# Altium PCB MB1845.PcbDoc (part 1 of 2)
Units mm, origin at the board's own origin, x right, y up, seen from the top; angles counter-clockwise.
Board outline 43.1 x 47.12 mm, 4 copper layers (Top Layer, Internal 1, Internal 2, Bottom Layer), stack 1.565 mm thick; 96 components, 86 nets, 349 pads, 596 vias.
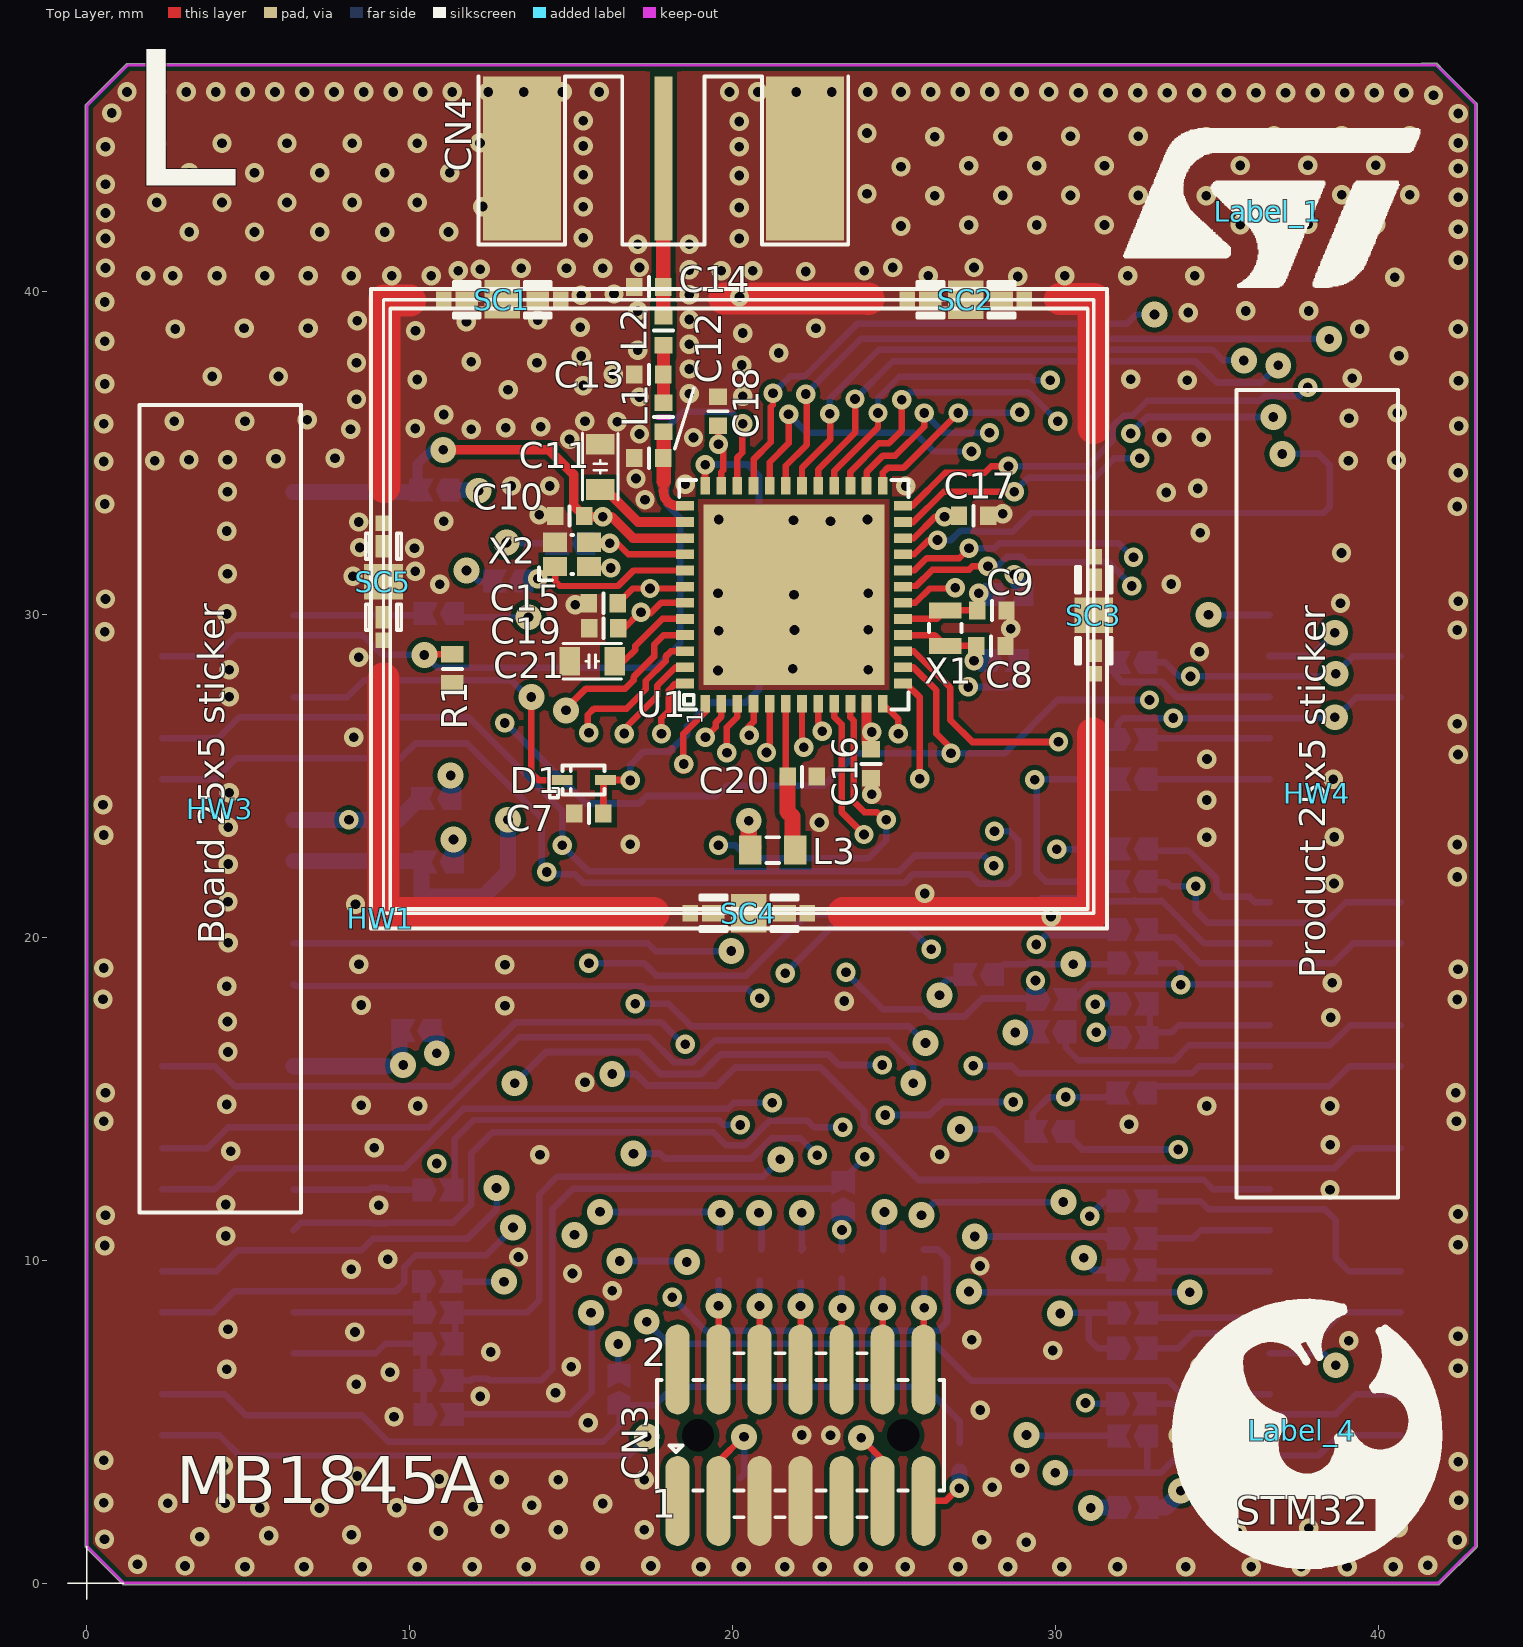
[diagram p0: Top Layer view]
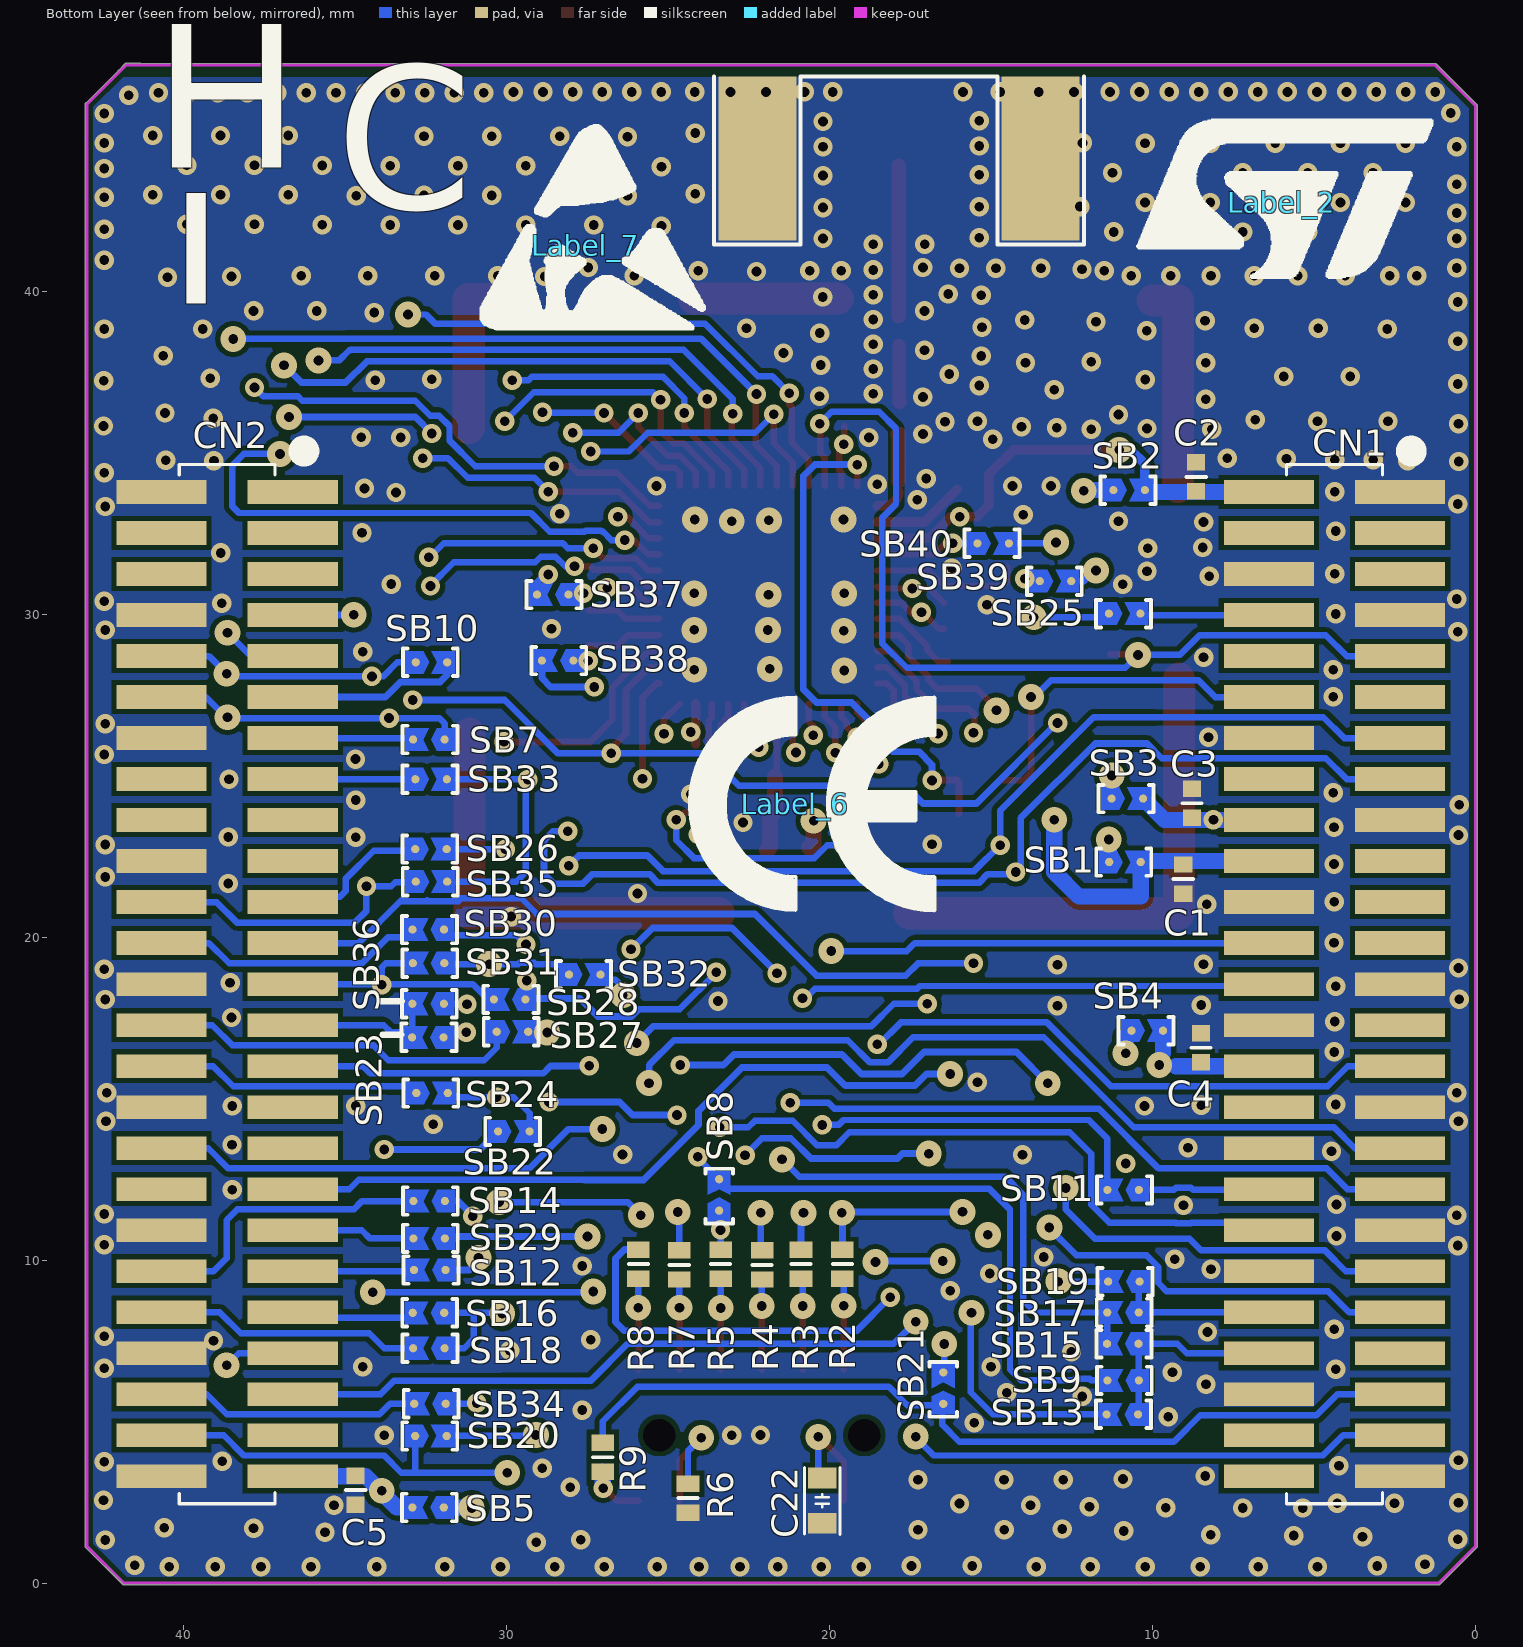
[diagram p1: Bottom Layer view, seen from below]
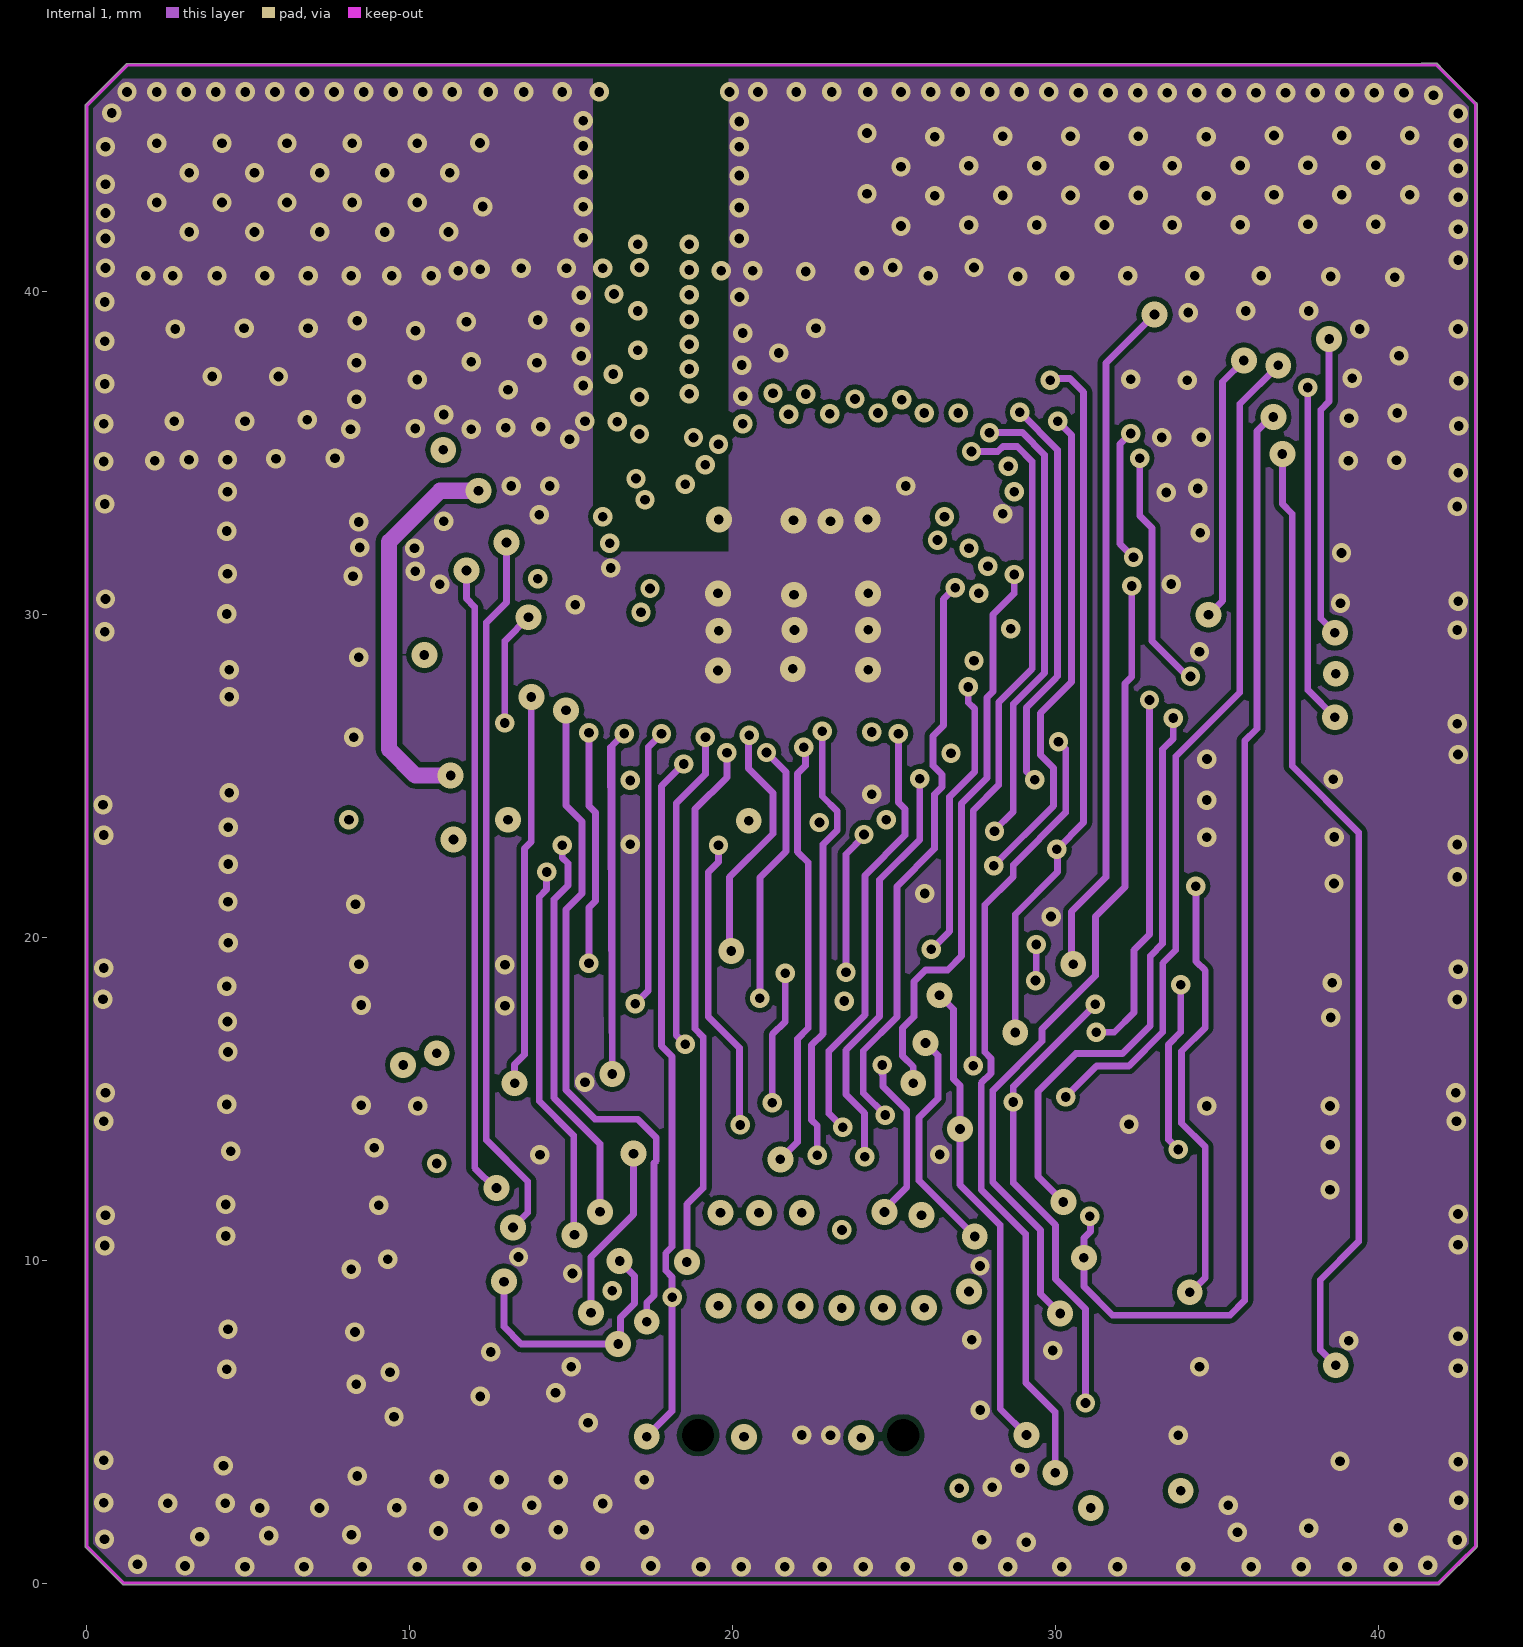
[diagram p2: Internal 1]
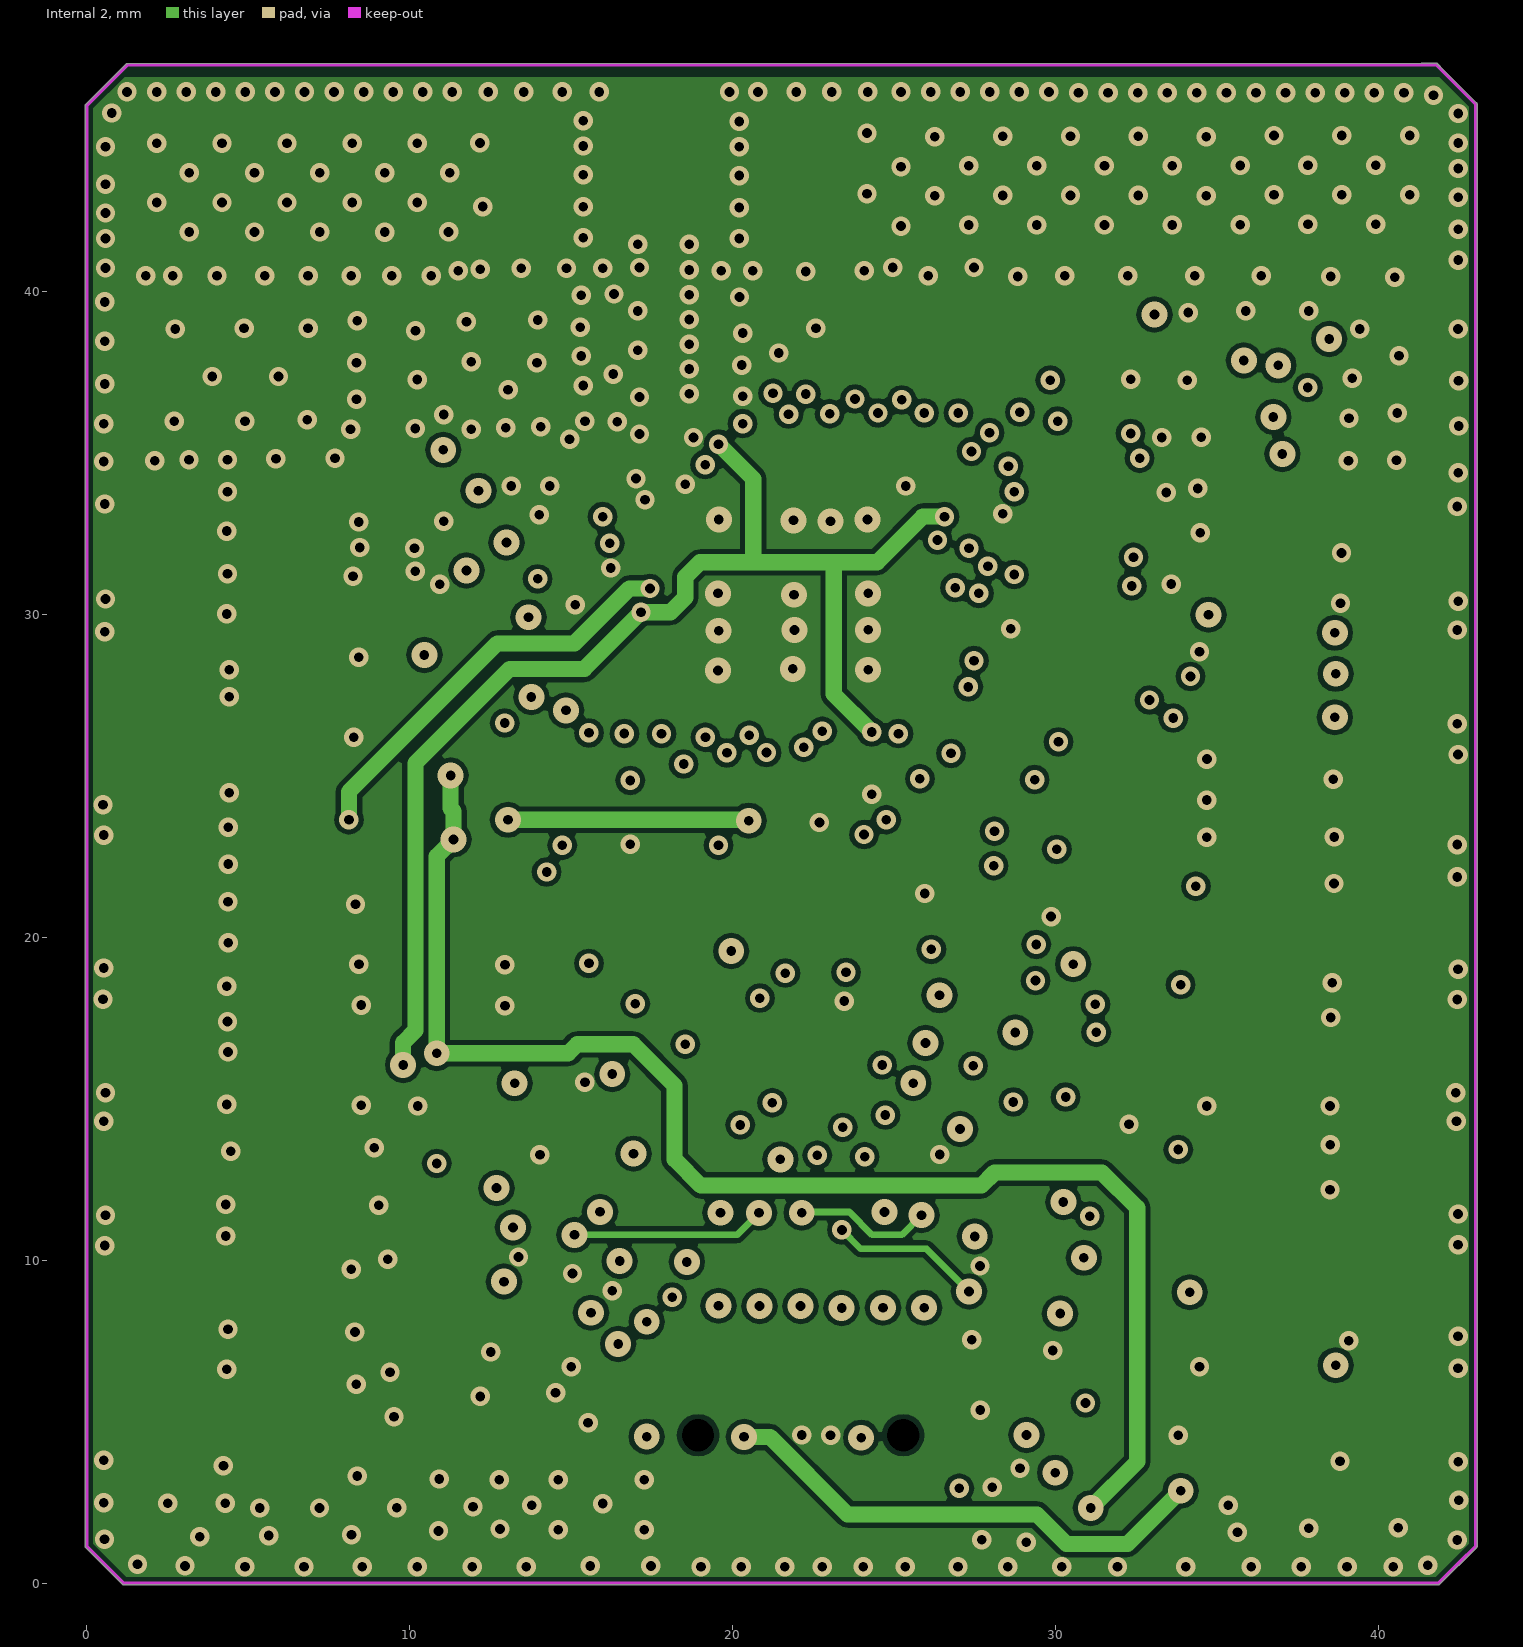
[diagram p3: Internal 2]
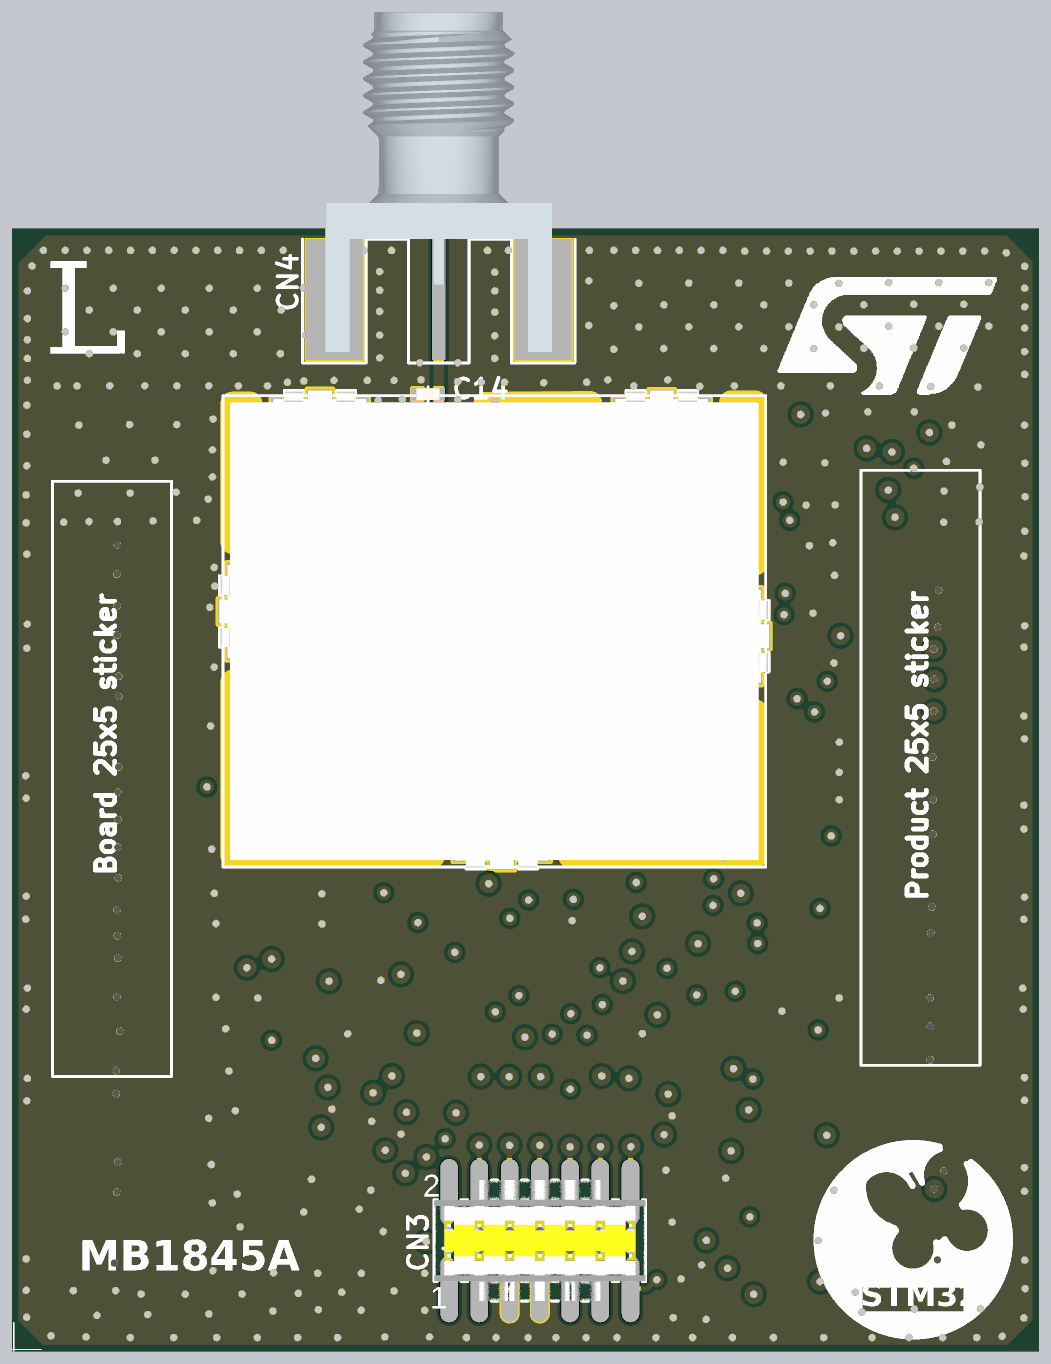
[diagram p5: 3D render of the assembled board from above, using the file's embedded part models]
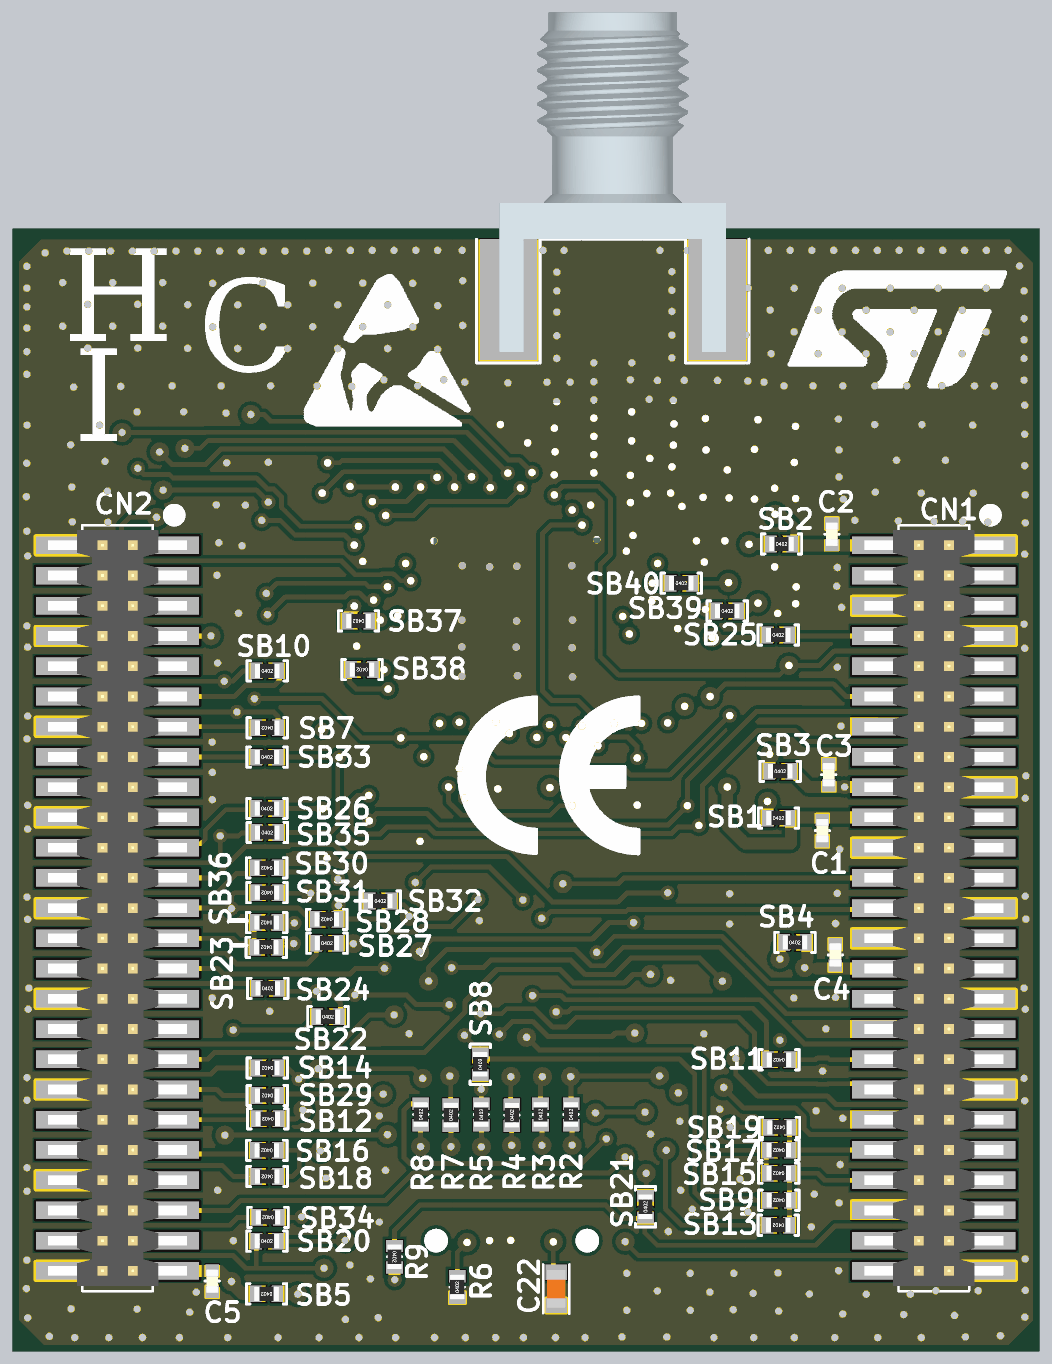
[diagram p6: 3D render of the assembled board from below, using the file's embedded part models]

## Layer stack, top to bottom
Top Solder: solder mask 0.0178, Solder Resist, Dk 4.2
Top Layer: signal copper 0.0406
Dielectric 1: core 0.0762, FR-4, Dk 3.7
Internal 1: signal copper 0.0305
Dielectric 3: prepreg 1.27, Dk 4.5
Internal 2: signal copper 0.0305
Dielectric 2: core 0.0762, Dk 3.7
Bottom Layer: signal copper 0.0406
Bottom Solder: solder mask 0.0178, Solder Resist, Dk 4.2

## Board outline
-0.036,1.103 cw(c0,1.139) -0.05,1.139 -0.05,45.75 -0.05,45.755 cw(c0,45.755) -0.035,45.791 -0.036,45.791 1.209,47.036 1.209,47.035 cw(c1.245,47) 1.245,47.05 41.326,47.066 cw(c41.326,47.015) 41.326,47.066 41.78,47.066 cw(c41.78,47.015) 41.816,47.051 42.023,46.844 43.03,45.837 cw(c43.001,45.795) 43.051,45.795 cw(c43.001,45.795) 43.05,45.785 43.05,1.151 cw(c43.001,1.141) 43.051,1.141 cw(c43.001,1.141) 43.037,1.105 41.888,-0.036 cw(c41.852,0) 41.852,-0.05 1.139,-0.05 cw(c1.139,0) 1.103,-0.036

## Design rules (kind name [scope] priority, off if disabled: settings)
Clearance "RF Path 3" [InNet('NetC12_2')] p1: gap=0.13 ignorepadtopadclearanceinfootprint=FALSE
Clearance "RF Path 2" [InNet('NetC13_2')] p2: gap=0.13 ignorepadtopadclearanceinfootprint=FALSE
Clearance "RF Path 1" [InNet('ANT')] p3: gap=0.13 ignorepadtopadclearanceinfootprint=FALSE
Clearance [All] p4: gap=0.15 ignorepadtopadclearanceinfootprint=FALSE
ComponentClearance [All] p1: gap=0.2 collisioncheckmode=3 verticalgap=0.2 showdistances=FALSE
HoleSize [All] p1: absolutevalues=TRUE maxlimit=10 minlimit=0.025 maxpercent=80.000 minpercent=20.000
MinimumSolderMaskSliver [All] p1 off: minsoldermaskwidth=0.1
PasteMaskExpansion [All] p1 off: expansion=0
PlaneConnect [All] p1: planeconnectstyle=Relief reliefexpansion=0.508 reliefentries=4 reliefconductorwidth=0.21 reliefairgap=0.21
PolygonConnect Path_RF [InNet('NetC12_2')] p1: connectstyle=Direct reliefconductorwidth=0.254 reliefentries=4 polygonreliefangle="90 Angle" airgapwidth=0.254
PolygonConnect PolygonConnect_via [IsVia] p2: connectstyle=Direct reliefconductorwidth=0.254 reliefentries=4 polygonreliefangle="90 Angle" airgapwidth=0.254
PolygonConnect General [All] p3: connectstyle=Direct reliefconductorwidth=0.2 reliefentries=4 polygonreliefangle="90 Angle" airgapwidth=0.2
RoutingVias [All] p1: holewidth=0.3 width=0.8 viastyle="Through Hole" minholewidth=0.2 minwidth=0.5 maxholewidth=3.5 maxwidth=6.5
SilkToSilkClearance [All] p1 off: silktosilkclearance=0.2
SilkToSolderMaskClearance [IsPad] p1 off: minsilkscreentomaskgap=0.2 clearancetoexposedcopper=TRUE
SolderMaskExpansion [All] p1 off: expansion=0.102 istentingtop=FALSE
Width [All] p1: maxlimit=6 minlimit=0.15 preferedwidth=0.254 toplayer_prefwidth=0.2 midlayer1_minwidth=0.21 midlayer1_maxwidth=0.512 midlayer2_minwidth=0.21 midlayer2_maxwidth=0.512 bottomlayer_prefwidth=0.2 minimp=50.000000 maximp=50.000000 favimp=50.000000
23 further rules are at their usual default settings.

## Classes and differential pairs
component class "STM32 microcontroller I/Os & Clock": C1 C2 C3 C4 C5 C7 C8 C9 CN1 CN2 D1 R1 SB1 SB2 SB3 SB4 SB5 SB7 SB8 SB9 SB10 SB11 SB12 SB13 SB14 SB15 SB16 SB17 SB18 SB19 SB20 SB21 SB22 SB23 SB24 SB25 SB26 SB27 SB28 SB29 SB30 SB31 SB32 SB33 SB34 SB35 SB36 SB37 SB38 SB39 SB40 U1 X1 X2
component class "RF & Power Management Schematic": C10 C11 C12 C13 C14 C15 C16 C17 C18 C19 C20 C21 C22 CN3 CN4 HW1 L1 L2 L3 R2 R3 R4 R5 R6 R7 R8 R9 SC1 SC2 SC3 SC4 SC5
component class Project_Overview: HW2 HW3 HW4

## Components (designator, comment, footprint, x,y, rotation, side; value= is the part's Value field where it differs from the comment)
C1 "Capacitor" C0402 9.05,21.804 r90 bottom value=1uF
C2 "Capacitor" C0402 8.649,34.255 r270 bottom value=1uF
C3 "Capacitor" C0402 8.782,24.151 r270 bottom value=1uF
C4 "Capacitor" C0402 8.504,16.581 r270 bottom value=1uF
C5 "Capacitor" C0402 34.678,2.881 r90 bottom value=1uF
C7 "Capacitor" C0402 15.547,23.83 r0 top value=100nF
C8 "Capacitor" C0402 27.997,29.021 r180 top value=6pF
C9 "Capacitor" C0402 28.027,30.119 r180 top value=6pF
C10 "Capacitor" C0402 14.951,33.045 r180 top value=100nF
C11 "Capacitor" C0603 15.9,34.566 r270 top value=470nF
C12 "Capacitor" C0402 17.404,34.835 r0 top value=1.5pF
C13 "Capacitor" C0402 17.404,37.43 r0 top value=1.8pF
C14 "Capacitor" C0402 17.404,40.142 r0 top value=1pF
C15 "Capacitor" C0402 15.996,30.342 r180 top value=100nF
C16 "Capacitor" C0402 24.281,25.37 r270 top value=100nF
C17 "Capacitor" C0402 27.457,33.052 r0 top value=100nF
C18 "Capacitor" C0402 19.546,36.287 r90 top value=100nF
C19 "Capacitor" C0402 16.004,29.571 r180 top value=100nF
C20 "Capacitor" C0402 22.147,24.972 r180 top value=1uF
C21 "Capacitor" C0603_H0P8 15.649,28.545 r0 top value=4.7uF
C22 "Capacitor" C0603 20.231,2.554 r90 bottom value=1uF
CN1 "FTSH-125-02-L-DV" FTSH-125-02-L-DV 4.366,18.548 r180 bottom locked value="Header 25x2"
CN2 "FTSH-125-02-L-DV" FTSH-125-02-L-DV 38.656,18.548 r180 bottom locked value="Header 25x2"
CN3 "Header 7x2" CON_SAMTEC_FTSH-107-01-L-DV-K-A 22.101,4.579 r0 top
CN4 "SMA-J-P-H-ST-EM1" CON_SMA-RF_CINCH_142-0701-851 17.854,46.65 r0 top value=Jack_SMA_142-0701-851
D1 "SCHOTTKY_1A_2K" DIO_SOD523_1A_2K 15.384,24.869 r180 top value=BAT54KFILM
Designator14 "Comment" PCB_SPECIFICATIONS -3.124,121.133 r0 top
Designator15 "Comment" Sheetbox_4L2S 51.892,-13.183 r0 top
Designator16 "Comment" IMPEDANCE_TABLE -4.013,161.315 r0 top
HW1 "RF Shield (22.2x19.2x2mm)" SHIELD_RF_ST-CUSTOM_22P2X19P2_H2 9.093,20.574 r0 top
HW3 "STICKER_BOARD" STICKER_BOARD_25X5 4.126,23.98 r90 top value="Sticker board"
HW4 "STICKER_PRODUCT" STICKER_PRODUCT_25X5 38.095,24.445 r90 top value="Sticker product"
L1 "Inductor" C0402 17.854,36.106 r90 top value=3.3nH
L2 "Inductor" C0402 17.854,38.786 r90 top value=3.3nH
L3 "Inductor" IND_0603_H0P8 21.241,22.697 r0 top value="47R @ 100MHz"
Label_1 "LOGO_ST" LOGO_ST_Size3 36.588,42.487 r0 top
Label_2 "LOGO_ST" LOGO_ST_Size3 6.004,42.76 r180 bottom
Label_4 "LOGO_STM32" LOGO_STM32 37.633,4.734 r0 top
Label_6 "LOGO_CE" "LOGO CE" 21.069,24.132 r180 bottom
Label_7 "LOGO_ESD" "LOGO ESD" 27.547,41.437 r180 bottom
R1 "Resistor" R0402 11.319,28.312 r270 top value=100K
R2 "Resistor" R0402 19.605,9.878 r90 bottom value=47R
R3 "Resistor" R0402 20.887,9.878 r90 bottom value=47R
R4 "Resistor" R0402 22.092,9.852 r90 bottom value=47R
R5 "Resistor" R0402 23.376,9.878 r90 bottom value=47R
R6 "Resistor" R0402 24.386,2.631 r90 bottom value=47R
R7 "Resistor" R0402 24.658,9.853 r90 bottom value=47R
R8 "Resistor" R0402 25.922,9.878 r90 bottom value=47R
R9 "Resistor" R0402 27.024,3.9 r270 bottom value=47R
SB1 "SB_OFF" SOLDER-BRIDGE_R0402-0R 10.893,22.329 r180 bottom
SB2 "SB_OFF" SOLDER-BRIDGE_R0402-0R 10.764,33.846 r180 bottom
SB3 "SB_OFF" SOLDER-BRIDGE_R0402-0R 10.819,24.295 r180 bottom
SB4 "SB_OFF" SOLDER-BRIDGE_R0402-0R 10.201,17.107 r180 bottom
SB5 "SB_OFF" SOLDER-BRIDGE_R0402-0R 32.397,2.343 r0 bottom
SB7 "SB_ON" SOLDER-BRIDGE_R0402-0R 32.372,26.123 r0 bottom
SB8 "SB_OFF" SOLDER-BRIDGE_R0402-0R 23.421,11.984 r90 bottom
SB9 "SB_ON" SOLDER-BRIDGE_R0402-0R 10.875,6.277 r0 bottom
SB10 "SB_ON" SOLDER-BRIDGE_R0402-0R 32.367,28.514 r180 bottom
SB11 "SB_ON" SOLDER-BRIDGE_R0402-0R 10.874,12.177 r0 bottom
SB12 "SB_ON" SOLDER-BRIDGE_R0402-0R 32.347,9.698 r0 bottom
SB13 "SB_OFF" SOLDER-BRIDGE_R0402-0R 10.898,5.226 r0 bottom
SB14 "SB_ON" SOLDER-BRIDGE_R0402-0R 32.364,11.832 r0 bottom
SB15 "SB_OFF" SOLDER-BRIDGE_R0402-0R 10.885,7.413 r0 bottom
SB16 "SB_ON" SOLDER-BRIDGE_R0402-0R 32.385,8.371 r0 bottom
SB17 "SB_ON" SOLDER-BRIDGE_R0402-0R 10.878,8.381 r0 bottom
SB18 "SB_ON" SOLDER-BRIDGE_R0402-0R 32.373,7.274 r0 bottom
SB19 "SB_OFF" SOLDER-BRIDGE_R0402-0R 10.85,9.337 r0 bottom
SB20 "SB_OFF" SOLDER-BRIDGE_R0402-0R 32.383,4.557 r180 bottom
SB21 "SB_ON" SOLDER-BRIDGE_R0402-0R 16.481,6.002 r90 bottom
SB22 "SB_OFF" SOLDER-BRIDGE_R0402-0R 29.816,13.988 r180 bottom
SB23 "SB_ON" SOLDER-BRIDGE_R0402-0R 32.405,16.901 r0 bottom
SB24 "SB_ON" SOLDER-BRIDGE_R0402-0R 32.35,15.176 r180 bottom
SB25 "SB_OFF" SOLDER-BRIDGE_R0402-0R 10.902,30.022 r180 bottom
SB26 "SB_ON" SOLDER-BRIDGE_R0402-0R 32.383,22.731 r180 bottom
SB27 "SB_OFF" SOLDER-BRIDGE_R0402-0R 29.86,17.075 r180 bottom
SB28 "SB_OFF" SOLDER-BRIDGE_R0402-0R 29.871,18.075 r0 bottom
SB29 "SB_ON" SOLDER-BRIDGE_R0402-0R 32.366,10.674 r0 bottom
SB30 "SB_ON" SOLDER-BRIDGE_R0402-0R 32.393,20.239 r0 bottom
SB31 "SB_ON" SOLDER-BRIDGE_R0402-0R 32.382,19.199 r0 bottom
SB32 "SB_OFF" SOLDER-BRIDGE_R0402-0R 27.619,18.845 r180 bottom
SB33 "SB_ON" SOLDER-BRIDGE_R0402-0R 32.377,24.893 r180 bottom
SB34 "SB_ON" SOLDER-BRIDGE_R0402-0R 32.34,5.556 r0 bottom
SB35 "SB_OFF" SOLDER-BRIDGE_R0402-0R 32.367,21.723 r180 bottom
SB36 "SB_OFF" SOLDER-BRIDGE_R0402-0R 32.396,17.941 r0 bottom
SB37 "SB_OFF" SOLDER-BRIDGE_R0402-0R 28.537,30.612 r0 bottom
SB38 "SB_OFF" SOLDER-BRIDGE_R0402-0R 28.386,28.569 r0 bottom
SB39 "SB_OFF" SOLDER-BRIDGE_R0402-0R 13.043,31.029 r180 bottom
SB40 "SB_OFF" SOLDER-BRIDGE_R0402-0R 14.974,32.198 r180 bottom
SC1 "Shield-clip_S0951-46R" CLIP_HARWIN_S0951-46R#1 12.862,39.742 r180 top value=S0951-46R
SC2 "Shield-clip_S0951-46R" CLIP_HARWIN_S0951-46R#2 27.222,39.742 r180 top value=S0951-46R
SC3 "Shield-clip_S0951-46R" CLIP_HARWIN_S0951-46R#2 31.182,29.971 r90 top value=S0951-46R
SC4 "Shield-clip_S0951-46R" CLIP_HARWIN_S0951-46R#2 20.502,20.745 r180 top value=S0951-46R
SC5 "Shield-clip_S0951-46R" CLIP_HARWIN_S0951-46R#2 9.185,31.013 r90 top value=S0951-46R
U1 "STM32WBA52CGU6" ICC_UFQFPN48-EPAD_7X7_H0P55_P050 21.895,30.608 r90 top locked
X1 "XTAL_2_PINS" CRY_NX1610SE_2P 26.581,29.572 r270 top value=32.768kHz
X2 "XTAL_4_PINS" CRY_NX1612SA_4P 15.026,31.855 r0 top value=32MHz

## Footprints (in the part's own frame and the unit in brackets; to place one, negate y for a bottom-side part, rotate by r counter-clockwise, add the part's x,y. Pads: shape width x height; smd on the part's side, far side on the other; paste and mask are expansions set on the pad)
C0402 [mm]
  rect 0.51x0.56 smd mask+0.05: 1(-0.45,0) 2(0.45,0)
  silkscreen extent 0,-0.3 0,0.3, body extent -0.5,-0.3 0.5,0.3, height 0.4
C0603 [mm]
  rect 0.64x0.89 smd mask+0.05: 1(-0.7,0) 2(0.7,0)
  silkscreen extent -1.05,-0.55 1.02,0.55, body extent -0.9,-0.5 0.9,0.5, height 1.4
C0603_H0P8 [mm] "MCD-01540"
  rect 0.64x0.89 smd mask+0.05: 1(-0.7,0) 2(0.7,0)
  silkscreen extent -0.9,-0.55 0.9,0.55, body extent -0.9,-0.5 0.9,0.5, height 1
CLIP_HARWIN_S0951-46R#1 [mm] "MCD-01587_CLIP-X1"
  rect 0.48x0.5 smd mask+0.1: 1(-1.81,0) 1(1.81,0)
  rect 0.7x0.5 smd mask+0.1: 1(-1.1,0) 1(1.1,0)
  rect 1.1x1.2 smd mask+0.1: 1(0,-0.013)
  silkscreen extent -1.5,-0.55 1.5,0.55, body extent -2.05,-0.65 2.05,0.65, height 1.28
CLIP_HARWIN_S0951-46R#2 [mm] "MCD-01587_CLIP-X1"
  rect 0.48x0.5 smd mask+0.1: 1(-1.81,0) 1(1.81,0)
  rect 0.7x0.5 smd mask+0.1: 1(-1.1,0) 1(1.1,0)
  rect 1.1x1.2 smd mask+0.1: 1(0,0)
  silkscreen extent -1.5,-0.55 1.5,0.55, body extent -2.05,-0.65 2.05,0.65, height 1.28
CON_SAMTEC_FTSH-107-01-L-DV-K-A [mm] "MCD-01959"
  oval 0.74x2.79 smd mask+0.05: 1(-3.81,-2.035) 2(-3.81,2.035) 3(-2.54,-2.035) 4(-2.54,2.035) 5(-1.27,-2.035) 6(-1.27,2.035) 7(0,-2.035) 8(0,2.035) 9(1.27,-2.035) 10(1.27,2.035) 11(2.54,-2.035) 12(2.54,2.035) 13(3.81,-2.035) 14(3.81,2.035)
  round 0 hole 1 unplated paste-10 mask+0.05: NPTH1(-3.175,0) NPTH2(3.175,0)
  silkscreen extent -4.44,-2.54 4.44,2.54, body extent -4.44,-2.92 4.45,2.92, height 6.12
CON_SMA-RF_CINCH_142-0701-851 [mil] "MCD-02072"
  rect 21.65x200 smd mask+1.97: 1(0,-100)
  rect 95x200 smd mask+1.97: 2(172.48,-100) 3(-172.48,-100)
  rect 95x200 smd far side mask+1.97: 4(-172.48,-100) 5(172.48,-100)
  silkscreen extent -225,-205 225,0, body extent -189,-187 189,376, height 161
CRY_NX1610SE_2P [mm] "MCD-02291"
  rect 0.5x1 smd mask+0.05: 1(-0.55,0) 2(0.55,0)
  silkscreen extent -0.13,-0.5 0.13,0.5, body extent -0.8,-0.5 0.8,0.5, height 0.45
CRY_NX1612SA_4P [mm] "MCD-02262"
  rect 0.75x0.6 smd mask+0.038: 1(-0.525,-0.375) 2(0.525,-0.375) 3(0.525,0.375) 4(-0.525,0.375)
  silkscreen extent -1.02,-0.8 0.03,0.6, body extent -0.8,-0.6 0.8,0.6, height 0.51
DIO_SOD523_1A_2K [mm] "MCD-01677"
  rect 0.65x0.3 smd mask+0.05: 1(-0.675,0) 2(0.675,0)
  silkscreen extent -0.65,-0.45 1.05,0.55, body extent -0.85,-0.45 0.85,0.45, height 0.71
FTSH-125-02-L-DV [mil] "Header2x25 Reverse 1.27mm SAMTEC (FTSH-125-02-L-DV)"
  rect 110x29.02 smd: 1(80,600) 2(-80,600) 3(80,550) 4(-80,550) 5(80,500) 6(-80,500) 7(80,450) 8(-80,450) 9(80,400) 10(-80,400) 11(80,350) 12(-80,350) 13(80,300) 14(-80,300) 15(80,250) 16(-80,250) 17(80,200) 18(-80,200) 19(80,150) 20(-80,150) 21(80,100) 22(-80,100) 23(80,50) 24(-80,50) 25(80,0) 26(-80,0) 27(80,-50) 28(-80,-50) 29(80,-100) 30(-80,-100) 31(80,-150) 32(-80,-150) 33(80,-200) 34(-80,-200) 35(80,-250) 36(-80,-250) 37(80,-300) 38(-80,-300) 39(80,-350) 40(-80,-350) 41(80,-400) 42(-80,-400) 43(80,-450) 44(-80,-450) 45(80,-500) 46(-80,-500) 47(80,-550) 48(-80,-550) 49(80,-600) 50(-80,-600)
  silkscreen extent -58,-633 103,659, body extent -115,-625 115,625, height 190
ICC_UFQFPN48-EPAD_7X7_H0P55_P050 [mm] "MCD-01704"
  rect 0.55x0.3 smd mask+0.05: 1(-3.375,2.75) 2(-3.375,2.25) 3(-3.375,1.75) 4(-3.375,1.25) 5(-3.375,0.75) 6(-3.375,0.25) 7(-3.375,-0.25) 8(-3.375,-0.75) 9(-3.375,-1.25) 10(-3.375,-1.75) 11(-3.375,-2.25) 12(-3.375,-2.75) 25(3.375,-2.75) 26(3.375,-2.25) 27(3.375,-1.75) 28(3.375,-1.25) 29(3.375,-0.75) 30(3.375,-0.25) 31(3.375,0.25) 32(3.375,0.75) 33(3.375,1.25) 34(3.375,1.75) 35(3.375,2.25) 36(3.375,2.75)
  rect 0.3x0.55 smd mask+0.05: 13(-2.75,-3.375) 14(-2.25,-3.375) 15(-1.75,-3.375) 16(-1.25,-3.375) 17(-0.75,-3.375) 18(-0.25,-3.375) 19(0.25,-3.375) 20(0.75,-3.375) 21(1.25,-3.375) 22(1.75,-3.375) 23(2.25,-3.375) 24(2.75,-3.375) 37(2.75,3.375) 38(2.25,3.375) 39(1.75,3.375) 40(1.25,3.375) 41(0.75,3.375) 42(0.25,3.375) 43(-0.25,3.375) 44(-0.75,3.375) 45(-1.25,3.375) 46(-1.75,3.375) 47(-2.25,3.375) 48(-2.75,3.375)
  rect 5.6x5.6 smd mask+0.05: 49(0,0)
  silkscreen extent -3.55,-3.55 3.55,3.55, body extent -3.5,-3.5 3.5,3.5, height 0.65
IMPEDANCE_TABLE [mm]
IND_0603_H0P8 [mm]
  rect 0.7x0.9 smd mask+0.05: 1(-0.7,0) 2(0.7,0)
  silkscreen extent -0.2,-0.4 0.2,0.4, body extent -0.8,-0.4 0.8,0.4, height 0.8
"LOGO CE" [mm]
  silkscreen extent -3.27,-3.31 4.33,3.3
"LOGO ESD" [mm]
  silkscreen extent -3.23,-2.59 3.66,3.68
LOGO_ST_Size3 [mm]
  silkscreen extent -4.5,-2.36 4.7,2.57
LOGO_STM32 [mm]
  silkscreen extent -3.9,-4.23 4.33,3.95
PCB_SPECIFICATIONS [mm]
R0402 [mm]
  rect 0.51x0.7 smd mask+0.05: 1(-0.45,0) 2(0.45,0)
  silkscreen extent 0,-0.3 0,0.3, body extent -0.52,-0.3 0.52,0.3, height 0.4
Sheetbox_4L2S [mil] "Sheetbox 4 layers / 2 silkscreens"
  round 20 on Mech16: 1(813.78,210.69) 1(2736.9,210.69)
SHIELD_RF_ST-CUSTOM_22P2X19P2_H2 [mm] "MCD-02088"
  silkscreen extent -0.3,-0.3 22.5,19.5, body extent 0,0 22.2,19.2, height 2.45
SOLDER-BRIDGE_R0402-0R [mil] "MCD-01619"
  round 10 smd paste-393.7: 1(-17.72,0) 2(20.67,0)
  Top Layer region: -30.51,-13.78 -30.51,13.78 -8.37,13.78 -1.48,0 -8.37,-13.78
  Top Layer region: 1.48,13.78 8.37,0 1.48,-13.78 30.51,-13.78 30.51,13.78
  silkscreen extent -33,-17 33,17, body extent -20,-12 20,12, height 14
STICKER_BOARD_25X5 [mm] "Sticker to mention board reference + serial number"
  silkscreen extent -12.5,-2.5 12.5,2.5, body extent -12.5,-2.5 12.5,2.5, height 0.01
STICKER_PRODUCT_25X5 [mm] "Sticker to mention board CPN code"
  silkscreen extent -12.5,-2.5 12.5,2.5

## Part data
C1 C2 C3 C4 C5 C20: library part MCD-01722, "Capacitor, MLCC, 1uF, 10V, X5R, +/-10%, 0402, T=0.5mm", Manufacturer=YAGEO, Manufacturer_Part_Number=CC0402KRX5R6BB105, Package=0402
C7 C10 C15 C16 C17 C18 C19: library part MCD-00006, "Capacitor, MLCC, 100nF, 16V, X7R, +/-10%, 0402, T=0.5mm", Alternate_Manufacturer=MURATA, Alternate_Manufacturer_Part_Number=GCM155R71C104KA55D, Manufacturer=YAGEO, Manufacturer_Part_Number=CC0402KRX7R7BB104, Package=C0402
C8 C9: library part MCD-03185, "6 pF ±0,25pF 50V Condensateurs céramique C0G, NP0 0402 (1005 métrique)", Manufacturer=MURATA, Manufacturer_Part_Number=GJM1555C1H6R0CB01, Package=0402
C11: library part MCD-01006, "Capacitor, MLCC, 470nF, 16V, X7R, +/-10%, 0603, T=0.8mm", Manufacturer=YAGEO, Manufacturer_Part_Number=CC0603KRX7R7BB474, Package=0603
C12: library part MCD-02994, "Capacitor, MLCC, 1.5pF, 50V, C0G, +/-0.25pF, 0402, T=0.5mm", Manufacturer=MURATA, Manufacturer_Part_Number=GRM1555C1H1R5CA01, Package=0402
C13: library part MCD-02995, "Capacitor, MLCC, 1.8pF, 50V, C0G, +/-0.25pF, 0402, T=0.5mm", Manufacturer=MURATA, Manufacturer_Part_Number=GRM1555C1H1R8CA01, Package=0402
C14: library part MCD-01600, "Capacitor, MLCC, 1pF, 50V, NPO, +/-0.1pF, 0402, T=0.5mm", Manufacturer=YAGEO, Manufacturer_Part_Number=CC0402BRNPO9BN1R0, Package=0402
C21: library part MCD-01721, "Capacitor, MLCC, 4.7uF, 10V, X5R, +/-10%, 0603, T=0.8mm", Manufacturer=YAGEO, Manufacturer_Part_Number=CC0603KRX5R6BB475, Package=0603
C22: library part MCD-00010, "Capacitor, MLCC, 1uF, 16V, X5R, 10%, 0603, T=0,8mm", Manufacturer=YAGEO, Manufacturer_Part_Number=CC0603KRX5R7BB105, Package=C0603
CN1 CN2: library part MCD-02746, "Header, 25x2, 12.7mm, VR, SMD, T=4.83mm", Manufacturer=SAMTEC
CN3: library part MCD-01531, "Header, 7x2, 1.27mm, VR, T=5.97mm, FTSH series STDC14 without Alignment Pin", Manufacturer=SAMTEC, Manufacturer_Part_Number=FTSH-107-01-L-DV-K
CN4: library part MCD-02072, "Jack_SMA, VR, PCB edge, 50R, T=7.92mm", Alternate_Manufacturer=N/A, Manufacturer=JOHNSON, Manufacturer_Part_Number=142-0701-851
D1: library part MCD-01677, "Small signal Schottky diodes", Manufacturer=STMICROELECTRONICS, Manufacturer_HQ_COO=EU, Manufacturer_Part_Number=BAT54KFILM, Package=SOD-523
Designator14 Designator15 Designator16: library part MCD-00279
HW1: library part MCD-03256, Manufacturer=TBD
HW3: library part MCD-02190, "Sticker board 25x5 mm", Alternate_Manufacturer=N/A
HW4: library part MCD-02189, "Sticker product 25x5 mm", Alternate_Manufacturer=N/A
L1 L2: library part MCD-03001, "Inductor, 3.3nH, +/-0.3nH, 800 mA, 0.125Ohm, 0402, T=0.5mm", Manufacturer=MURATA, Manufacturer_Part_Number=LQG15HS3N3S02, Package=0402
L3: library part MCD-02587, "Ferrite bead, 47R @ 100MHz, +/-25%, 3.5A, 0R02, 0603, T=0.8mm", Manufacturer="TAIYO YUDEN", Manufacturer_Part_Number=FBMH1608HM470-T, Package=0603
R1: library part MCD-00059, "Resistor, 100K, 0402, +/-1%, 1/16W", Manufacturer=YAGEO, Manufacturer_Part_Number=RC0402FR-07100KL, Package=0402
R2 R3 R4 R5 R6 R7 R8 R9: library part MCD-00481, "Resistor,47R,0402,1%,1/16W", Manufacturer=YAGEO, Manufacturer_Part_Number=RC0402FR-0747RL, Package=R0402
SB1 SB2 SB3 SB4 SB5 SB8 SB13 SB15 SB19 SB20 SB22 SB25 SB27 SB28 SB32 SB35 SB36 SB37 SB38 SB39 SB40: library part MCD-02162, "Solder Bridge 0402 OFF", Manufacturer=YAGEO, Manufacturer_Part_Number=RC0402JR-070RL, Package=SB0402
SB7 SB9 SB10 SB11 SB12 SB14 SB16 SB17 SB18 SB21 SB23 SB24 SB26 SB29 SB30 SB31 SB33 SB34: library part MCD-01618, "Solder Bridge 0402 ON", Manufacturer=YAGEO, Manufacturer_Part_Number=RC0402JR-070RL, Package=SB0402
SC1 SC2 SC3 SC4 SC5: library part MCD-01587, "shield clip Harwin S0951-46R to fix RF shielded cavity", Manufacturer=HARWIN, Manufacturer_Part_Number=S0951-46R
U1: library part MCD-02741, "MCU,ARM Cortex M33,1MB Flash, 128KB SRAM, Crypto, RF 2.4GHz, BLE, 802.15.4", Manufacturer=STMICROELECTRONICS, Package="UFQFPN48 7X7 0.55"
X1: library part MCD-02579, "Crystal, 32.768kHz, 6pF, +/-20ppm, 70KR, 1.6x1mm", Manufacturer=NDK, Manufacturer_Part_Number=NX1610SE-32.768KHZ-EXS00A-MU01501, Package=1.6x1mm
X2: library part MCD-02578, "Crystal, 32MHz, 8pF, +/-10ppm, 40R, 1612(metric), T=0.3mm", Manufacturer=NDK, Manufacturer_Part_Number=NX1612SA-32MHZ-EXS00A-CS09166, Package=1612(metric)

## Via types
v1: diameter 0.6, hole 0.3, Top Layer to Bottom Layer, tented both sides, 513 vias
v2: diameter 0.8, hole 0.3, Top Layer to Bottom Layer, tented both sides, 83 vias

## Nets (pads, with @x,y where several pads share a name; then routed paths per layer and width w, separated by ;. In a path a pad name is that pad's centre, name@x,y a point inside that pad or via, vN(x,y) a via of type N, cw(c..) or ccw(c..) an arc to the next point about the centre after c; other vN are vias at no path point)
GND: C1.1 C2.1 C3.1 C4.1 C5.1 C7.1 C8.1 C9.1 C10.2 C11.1 C12.1 C13.1 C14.1 C15.2 C16.2 C17.2 C18.2 C19.2 C20.1 C21.1 C22.1 CN1.1 CN1.6 CN1.7 CN1.14 CN1.17 CN1.22 CN1.25 CN1.28 CN1.31 CN1.34 CN1.37 CN1.40 CN1.46 CN1.49 CN2.2 CN2.8 CN2.14 CN2.20 CN2.26 CN2.32 CN2.38 CN2.44 CN2.50 CN3.5 CN3.7 CN4.2 CN4.3 CN4.4 CN4.5 R1.2 R6.1 SC1.1 SC2.1 SC3.1 SC4.1 SC5.1 U1.49 X2.2 X2.4 | length 44.9
  Top Layer w1: 9.185,28.007 9.185,20.745 17.539,20.745 ; 9.21,33.949 9.21,39.718 9.995,39.718 ; 19.749,39.783 24.194,39.775 ; 23.432,20.742 31.153,20.742 31.153,26.305 ; 30.137,39.767 31.179,39.767 31.179,35.774
  other v1: 4.894,0.508 6.723,0.508 8.527,0.508 10.228,0.508 11.93,0.508 13.607,0.508 19.017,0.508 20.261,0.508 21.608,0.508 22.776,0.508 24.046,0.508 25.341,0.508 26.978,0.508 28.516,0.508 30.193,0.508 31.916,0.508 34.028,0.508 36.06,0.508 37.61,0.508 39.024,0.508 40.454,0.508 3.04,0.533 15.588,0.533 17.467,0.533 41.521,0.559 1.567,0.584 29.085,1.27 27.707,1.346 42.436,1.337 0.546,1.362 3.497,1.437 5.631,1.473 8.196,1.499 35.628,1.575 10.889,1.618 14.597,1.651 17.264,1.651 12.794,1.676 37.838,1.702 40.607,1.716 5.352,2.327 7.206,2.327 9.593,2.337 11.956,2.362 13.778,2.413 35.349,2.413 15.98,2.464 0.526,2.489 2.507,2.478 4.284,2.478 42.486,2.565 28.034,2.972 10.914,3.226 12.768,3.205 14.602,3.205 17.264,3.205 8.37,3.318 28.897,3.556 4.229,3.634 38.805,3.773 42.467,3.761 0.526,3.81 22.141,4.588 23.03,4.579 33.795,4.579 15.521,4.963 9.513,5.155 27.66,5.359 12.18,5.782 14.514,5.896 8.344,6.163 9.386,6.532 4.331,6.62 42.461,6.655 15.004,6.696 34.455,6.696 12.51,7.158 29.908,7.204 39.078,7.509 27.402,7.532 42.461,7.645 8.301,7.777 4.372,7.865 16.269,9.052 15.038,9.588 8.192,9.719 27.657,9.82 9.314,10.033 13.365,10.1 0.551,10.453 42.461,10.475 4.306,10.75 0.576,11.395 42.461,11.43 9.042,11.7 4.306,11.725 38.494,12.182 14.03,13.264 26.412,13.275 4.458,13.376 8.903,13.478 38.505,13.58 32.271,14.215 0.526,14.3 42.41,14.3 10.249,14.773 34.678,14.773 38.494,14.776 8.496,14.798 4.331,14.824 0.576,15.189 42.385,15.189 15.424,15.51 4.372,16.45 4.356,17.39 38.522,17.514 12.946,17.882 8.496,17.9 23.458,18.025 0.5,18.085 42.436,18.074 4.331,18.482 38.566,18.589 42.461,19.013 0.526,19.05 12.946,19.152 8.425,19.166 4.382,19.828 29.858,20.641 8.319,21.022 4.372,21.098 25.951,21.354 38.621,21.666 42.436,21.869 4.382,22.266 16.828,22.877 42.436,22.871 34.678,23.102 38.626,23.107 0.526,23.165 4.382,23.409 22.685,23.556 0.5,24.106 34.678,24.248 24.303,24.428 4.407,24.476 38.6,24.893 34.684,25.518 42.461,25.659 8.268,26.194 42.436,26.617 4.407,27.448 4.407,28.286 8.42,28.667 34.455,28.845 0.551,29.464 42.436,29.515 28.613,29.556 4.331,30.013 15.126,30.293 38.82,30.339 42.467,30.404 0.576,30.476 10.926,30.928 33.576,30.937 8.243,31.182 4.356,31.258 10.173,31.334 16.218,31.436 38.852,31.902 10.148,32.045 8.446,32.071 34.481,32.528 4.331,32.579 8.42,32.858 11.055,32.884 14.008,33.087 28.359,33.112 42.436,33.341 0.551,33.417 17.285,33.544 33.428,33.773 4.356,33.798 34.405,33.9 13.145,33.976 14.339,33.976 25.362,33.976 18.53,34.027 17.006,34.204 42.467,34.38 0.521,34.733 2.1,34.759 39.066,34.759 40.556,34.773 3.163,34.789 4.356,34.789 5.855,34.814 7.684,34.835 14.948,35.424 18.784,35.474 33.286,35.474 34.506,35.487 17.112,35.585 8.166,35.728 11.9,35.728 10.173,35.754 12.967,35.779 14.059,35.805 42.486,35.832 0.526,35.906 16.426,35.966 2.71,35.982 4.894,35.982 15.424,35.982 6.825,36.023 39.083,36.068 11.055,36.186 40.581,36.236 8.349,36.66 17.112,36.728 20.312,36.751 18.65,36.83 13.043,36.957 15.368,37.084 0.551,37.135 42.477,37.236 34.074,37.252 10.228,37.27 32.322,37.278 39.184,37.313 3.878,37.363 5.936,37.363 16.299,37.44 18.65,37.597 20.277,37.719 8.349,37.795 13.937,37.795 11.9,37.821 15.308,37.998 40.632,38.01 21.43,38.092 17.061,38.176 18.65,38.364 0.551,38.456 20.308,38.71 10.178,38.786 2.735,38.837 39.413,38.837 42.461,38.837 4.869,38.862 6.85,38.862 22.576,38.862 15.283,38.887 11.753,39.065 8.374,39.091 13.962,39.116 18.65,39.131 34.101,39.345 17.061,39.395 35.882,39.395 37.838,39.395 0.551,39.675 20.211,39.827 15.308,39.878 18.65,39.898 16.324,39.919 40.505,40.437 28.823,40.462 38.522,40.462 1.821,40.488 2.659,40.488 4.031,40.488 5.504,40.488 6.85,40.488 8.192,40.488 9.441,40.488 10.66,40.488 26.054,40.488 30.277,40.488 32.23,40.488 34.308,40.488 36.365,40.488 22.263,40.615 11.498,40.64 19.645,40.64 20.617,40.64 24.071,40.64 18.65,40.665 12.184,40.691 13.454,40.716 14.851,40.716 15.978,40.716 0.576,40.724 17.112,40.742 24.955,40.742 27.47,40.742 42.467,40.97 17.055,41.456 18.65,41.456 0.576,41.639 20.206,41.639 15.371,41.664 3.175,41.838 5.191,41.838 7.208,41.838 9.224,41.838 11.202,41.842 42.467,41.927 25.209,42.023 27.309,42.056 29.41,42.056 31.51,42.056 33.611,42.056 35.711,42.064 37.812,42.076 39.912,42.076 0.576,42.426 20.206,42.596 15.371,42.621 12.256,42.627 2.167,42.755 4.183,42.755 6.2,42.755 8.216,42.755 10.232,42.754 42.467,42.918 26.259,42.96 28.36,42.972 30.46,42.972 32.561,42.972 34.661,42.96 36.762,42.993 38.862,42.993 40.962,42.993 24.159,43.023 0.576,43.315 20.206,43.586 15.371,43.612 3.175,43.671 5.191,43.671 7.208,43.671 9.224,43.671 11.24,43.671 42.467,43.807 25.209,43.857 27.309,43.889 29.41,43.889 31.51,43.889 33.611,43.889 35.711,43.897 37.812,43.909 39.912,43.909 0.576,44.475 20.206,44.475 15.371,44.501 2.167,44.588 4.183,44.588 6.2,44.588 8.216,44.588 10.232,44.588 12.172,44.598 42.467,44.594 26.259,44.793 28.36,44.806 30.46,44.806 32.561,44.806 34.661,44.794 36.762,44.826 38.862,44.826 40.962,44.826 24.159,44.902 20.206,45.263 15.371,45.288 42.467,45.509 0.767,45.524 41.699,46.077 30.708,46.147 31.624,46.147 32.54,46.147 33.456,46.147 34.372,46.147 35.288,46.147 36.204,46.147 37.12,46.147 38.036,46.147 38.952,46.147 39.868,46.147 40.784,46.147 1.245,46.177 2.161,46.177 3.077,46.177 3.992,46.177 4.908,46.177 5.824,46.177 6.74,46.177 7.656,46.177 8.572,46.177 9.487,46.177 10.403,46.177 11.319,46.177 12.432,46.177 13.529,46.177 14.72,46.177 15.871,46.177 19.901,46.177 20.78,46.177 21.971,46.177 23.068,46.177 24.181,46.177 25.211,46.177 26.127,46.177 27.043,46.177 27.96,46.177 28.876,46.177 29.792,46.177
  other v2: 19.546,28.261 24.194,28.286 21.857,28.312 19.564,29.489 21.912,29.515 24.194,29.52 21.895,30.608 19.546,30.648 24.194,30.648 23.03,32.884 21.882,32.909 19.571,32.934 24.173,32.934
GPIO2: CN1.8 SB25.2 | length 4
  Bottom Layer w0.2: CN1.8@6.398,29.978 10.298,29.978 10.382,29.895
GPIO3/BOOT0: CN1.9 R1.1 U1.34 | length 29.4
  Top Layer w0.2: v2(10.452,28.743) 10.471,28.762 R1.1@11.319,28.762 ; U1.34@20.145,33.983 20.145,34.854 20.295,35.004 20.295,35.753 20.33,35.789 v1@20.33,35.837
  Bottom Layer w0.2: CN1.9@2.334,28.708 3.991,28.708 4.636,29.353 8.547,29.353 9.157,28.743 v2(10.452,28.743) 10.85,28.346 17.615,28.346 18.377,29.108 18.377,32.985 17.945,33.417 17.945,35.754 18.463,36.271 19.943,36.271 v1(20.308,35.906)
GPIO5/JTMS/SWDIO: CN1.13 R2.2 U1.27 | length 70
  Top Layer w0.2: U1.27@23.645,33.983 23.645,34.417 24.524,35.297 24.838,35.297 25.235,35.694 v1(25.235,36.643)
  Internal 1 w0.21: v1(14.72,22.851) 14.72,22.47 14.897,22.292 14.897,21.606 14.466,21.174 14.466,15.027 15.888,13.605 v2(15.888,11.497) ; v1(28.08,22.216) 29.934,24.07 29.934,25.238 29.528,25.645 29.528,26.94 30.493,27.905 30.493,35.551 v1(30.061,35.982)
  Bottom Layer w0.2: CN1.13@2.334,26.168 4.067,26.168 4.712,26.813 9.894,26.813 ; v1(25.235,36.643) 25.469,36.877 29.167,36.877 v1(30.061,35.982)
  Bottom Layer w0.21: 9.894,26.813 11.824,26.813 14.72,23.917 v1(14.72,22.851) 15.523,22.047 25.164,22.047 25.646,22.53 27.766,22.53 v1(28.08,22.216) ; v2(15.888,11.497) v2@19.564,11.497 ; R2.2@19.605,10.328 19.605,11.455 v2(19.622,11.471)
GPIO6/JTCK/SWCLK: CN1.15 R3.2 U1.26 | length 70.7
  Top Layer w0.2: U1.26@24.145,33.983 24.145,34.405 24.655,34.916 25.032,34.916 25.926,35.81 v1(25.926,36.236)
  Internal 1 w0.21: v1(14.237,22.022) 14.237,21.479 14.008,21.25 14.008,14.926 15.075,13.859 15.075,10.811 v2(15.101,10.786) ; v1(27.953,35.627) 28.969,35.627 29.655,34.941 29.655,28.185 28.69,27.219 28.69,23.892 v1@28.08,23.282
  Internal 2 w0.21: v2(15.101,10.786) 20.13,10.786 v2(20.811,11.467)
  Bottom Layer w0.2: CN1.15@2.334,24.898 3.991,24.898 4.636,25.543 9.716,25.543 ; v1(25.926,36.236) 26.536,35.627 v1(27.953,35.627)
  Bottom Layer w0.21: 9.716,25.543 10.173,26 11.773,26 14.085,23.689 14.085,22.139 14.27,21.954 15.107,21.954 15.374,21.687 25.313,21.687 25.579,21.954 27.34,21.954 27.633,21.661 28.549,21.661 28.842,21.954 28.842,23.003 28.563,23.282 v1(28.105,23.282) ; v2(20.811,11.467) 20.887,11.467 R3.2@20.887,10.328
GPIO11: CN1.24 U1.4 | length 22.4
  Top Layer w0.2: v1(20.511,26.254) 20.511,26.492 20.486,26.516 20.645,26.675 U1.4@20.645,27.233
  Internal 1 w0.21: v2(19.952,19.574) 20.003,19.574 19.901,19.676 19.901,21.86 21.247,23.206 21.247,24.464 20.485,25.226 20.485,26.229 v1(20.511,26.254) v1@20.511,26.225
  Bottom Layer w0.2: CN1.24@6.398,19.818 17.371,19.818 17.615,19.574 v2(19.952,19.574)
GPIO12: CN1.26 U1.5 | length 24.5
  Top Layer w0.2: v1@21.069,25.746 v1(21.044,25.721) 21.019,25.696 20.98,25.735 21.145,25.899 U1.5@21.145,27.233
  Internal 1 w0.21: v1(20.841,18.116) 20.841,21.852 21.649,22.661 21.649,25.116 v1(21.044,25.721)
  Bottom Layer w0.2: CN1.26@6.398,18.548 6.456,18.491 17.208,18.491 17.293,18.406 20.456,18.406 20.745,18.116 v1(20.841,18.116)
GPIO14: CN1.29 U1.2 | length 28.8
  Top Layer w0.2: v1(19.154,26.194) 19.154,26.184 19.47,26.5 19.47,26.648 19.645,26.823 U1.2@19.645,27.233
  Internal 1 w0.21: v1(18.53,16.688) 18.25,16.968 18.25,24.146 19.154,25.05 v1(19.154,26.194)
  Bottom Layer w0.2: CN1.29@2.334,16.008 3.953,16.008 4.579,15.383 11.291,15.383 13.272,17.364 17.791,17.364 v1@18.5,16.655
GPIO15/OSC32_IN: CN1.33 SB37.2 | length 44.7
  Internal 1 w0.21: v2(25.591,15.485) 25.591,15.993 25.261,16.323 25.261,17.186 25.616,17.542 25.616,18.634 25.972,18.99 26.658,18.99 27.085,19.417 27.085,24.142 27.877,24.933 27.877,27.425 28.058,27.606 28.058,29.992 28.715,30.648 v1(28.715,31.233)
  Bottom Layer w0.2: CN1.33@2.334,13.468 3.737,13.468 4.382,14.113 10.584,14.113 13.372,16.9 17.419,16.9 18.196,16.123 18.75,16.123 19.441,16.815 24.819,16.815 25.591,16.043 v2(25.591,15.485)
  Bottom Layer w0.21: v1(28.715,31.233) 28.817,31.233 29.062,30.987 SB37.2@29.062,30.612
GPIO16/OSC32_OUT: CN1.35 SB38.2 | length 40.6
  Internal 1 w0.21: v1(21.222,14.875) 21.222,16.983 21.628,17.39 v1(21.628,18.888) ; v1(26.15,19.625) 26.708,20.184 26.708,24.349 27.496,25.137 27.496,27.067 27.293,27.27 v1(27.293,27.753)
  Bottom Layer w0.2: CN1.35@2.334,12.198 3.966,12.198 4.61,12.843 9.815,12.843 11.67,14.697 19.861,14.697 20.038,14.875 v1(21.222,14.875)
  Bottom Layer w0.21: v1(21.628,18.888) 23.025,20.285 25.489,20.285 v1(26.15,19.625) ; v1@27.319,27.753 28.639,27.753 28.911,28.025 SB38.2@28.911,28.569
GPIO17: CN1.36 SB11.1 | length 4.1
  Bottom Layer w0.2: CN1.36@6.398,12.198 6.42,12.177 8.741,12.177 8.814,12.25 9.27,12.25 9.343,12.177 SB11.1@10.424,12.177
GPIO18: CN1.38 U1.12 | length 34.5
  Top Layer w0.2: U1.12@24.645,27.233 25.131,26.747 v1(25.131,26.305) v1@25.235,26.201
  Internal 1 w0.21: v1(23.406,14.113) 22.975,14.545 22.975,16.48 24.092,17.598 24.092,21.916 25.337,23.16 25.337,23.968 25.131,24.174 v1(25.131,26.305)
  Bottom Layer w0.2: CN1.38@6.398,10.928 6.637,11.167 8.797,11.167 8.814,11.15 9.27,11.15 9.286,11.167 11.342,11.167 11.899,11.723 11.899,13.298 12.561,13.961 19.393,13.961 19.8,13.554 20.379,13.554 21.141,14.316 22.314,14.316 22.517,14.113 v1(23.406,14.113)
GPIO21: CN1.42 SB17.1 SB19.1 | length 4.9
  Bottom Layer w0.2: CN1.42@6.398,8.388 SB17.1@10.375,8.388 ; SB17.1@10.428,8.381 SB19.1@10.428,9.309
GPIO22: CN1.44 SB9.1 SB13.1 SB15.1 | length 6.3
  Bottom Layer w0.2: CN1.44@6.398,7.118 8.944,7.118 9.239,7.413 SB15.1@10.435,7.413 SB13.1@10.435,5.239
GPIO23: CN1.45 R9.1 SB21.1 | length 27.6
  Bottom Layer w0.2: CN1.45@2.334,5.848 4.274,5.848 4.925,5.198 8.522,5.198 9.337,4.382 15.987,4.382 16.506,4.901 SB21.1@16.506,5.512 ; SB21.1@16.481,5.512 SB21.1@16.506,5.512 ; SB21.1@16.506,5.603 SB21.1@16.506,5.512 ; R9.1@27.024,4.35 27.024,5.009 25.952,6.081 18.164,6.081 17.596,5.512 SB21.1@16.506,5.512
GPIO24: CN1.47 R8.2 U1.1 | length 51.3
  Top Layer w0.2: v1@18.474,25.36 18.474,26.3 19.145,26.971 U1.1@19.145,27.233
  Top Layer w0.6: v1@18.474,25.36 v1(18.479,25.365)
  Internal 1 w0.21: v2(17.336,4.537) 18.123,5.325 v1(18.123,8.855) 18.123,9.478 17.925,9.676 17.925,10.219 18.123,10.416 18.123,16.31 17.793,16.64 17.793,24.679 v1(18.479,25.365)
  Bottom Layer w0.2: CN1.47@2.334,4.578 4.102,4.578 4.728,3.953 16.777,3.953 17.336,4.512 v2(17.336,4.537)
  Bottom Layer w0.21: v1(18.123,8.855) 19.165,7.814 26.353,7.814 26.632,8.093 26.632,10.049 26.353,10.328 R8.2@25.922,10.328
GPIO28: CN2.7 U1.30 | length 26.9
  Top Layer w0.2: U1.30@22.145,33.983 22.145,34.543 23.025,35.424 23.025,36.211 v1(23,36.211)
  Internal 1 w0.21: v2(34.735,29.988) 35.167,30.42 35.167,37.202 v2(35.827,37.862)
  Bottom Layer w0.2: v1(23,36.211) 23,36.668 24.523,38.191 34.832,38.191 34.845,38.178 34.876,38.178 35.192,37.862 v2(35.827,37.862)
  Bottom Layer w0.21: v2(34.735,29.988) 34.744,29.978 CN2.7@36.624,29.978
GPIO29: CN2.9 U1.31 | length 31.9
  Top Layer w0.2: U1.31@21.645,33.983 21.645,34.602 22.289,35.246 22.289,36.795 v1(22.263,36.821)
  Internal 1 w0.21: v2(38.469,38.528) 38.59,38.528 38.469,38.407 38.469,36.589 38.209,36.329 38.209,29.867 v2(38.646,29.429)
  Bottom Layer w0.2: v1(22.263,36.821) 23.984,38.541 34.977,38.541 34.99,38.528 v2(38.469,38.528)
  Bottom Layer w0.21: CN2.9@36.624,28.708 37.926,28.708 v2(38.646,29.429)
